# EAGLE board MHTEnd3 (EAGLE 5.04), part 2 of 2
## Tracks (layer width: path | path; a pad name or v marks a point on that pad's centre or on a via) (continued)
MASSE  (via drill 0.9 pad 1.5) (continued)
  Unten/V1 2.159: 144.53,142.24 143.26,140.97 143.26,136.91 | 143.26,136.91 143.26,135.89 144.53,134.62 148.34,134.62 | 150.88,129.54 G308.1 | 153.42,134.62 154.69,134.62 | 148.34,134.62 153.42,134.62 | 143.26,129.54 138.18,129.54 136.91,129.54 | 134.37,129.54 131.07,129.54 | 158.5,129.54 159.77,129.54 | 162.31,129.54 165.61,129.54 | 153.42,140.97 153.42,142.24 | 153.42,134.62 153.42,139.7 | 153.42,139.7 153.42,140.97 | 27.69,129.54 24.39,129.54 | 31.5,129.54 30.23,129.54 | 55.63,129.54 58.93,129.54 | 41.66,137.16 41.66,134.62 | 41.66,139.7 41.66,137.16 | 41.66,140.97 41.66,139.7 | 41.66,140.97 41.66,142.24 37.85,142.24 | 36.58,134.62 41.66,134.62 | 34.04,132.08 34.04,139.7 34.04,140.97 35.31,142.24 | 37.85,142.24 35.31,142.24 | 37.85,142.24 36.58,140.97 | 36.58,139.7 36.58,134.62 | 36.58,140.97 36.58,139.7 | 41.66,134.62 G117.2 | 36.58,132.08 36.58,134.62 | 35.31,142.24 35.31,132.08 | 153.42,140.97 152.15,142.24 | 149.61,142.24 152.15,142.24 | 148.34,142.24 149.61,142.24 | 148.34,142.24 144.53,142.24 | C105.2 37.85,185.42 | C108.1 42.93,185.42 | 96.27,201.93 J2.2 93.73,201.93 91.19,204.47 | C308.1 147.07,182.88 | C305.2 152.15,182.88 | 155.96,139.7 R315.2 | 158.25,129.79 158.25,133.6 155.96,135.89 | 152.15,142.24 149.61,144.78 | 144.53,142.24 144.53,143.51 | 41.66,139.7 36.58,139.7 | 36.58,140.97 41.66,140.97 | 45.47,143.51 45.47,142.24 46.74,140.97 46.74,138.43 45.47,137.16 | 45.47,137.16 42.93,134.62 41.66,134.62 | 40.39,144.78 37.85,142.24 | 41.66,137.16 45.47,137.16 | 44.2,143.51 41.66,140.97 | 153.42,139.7 152.15,139.7 | 152.15,139.7 149.61,142.24 | 148.34,136.91 148.34,139.7 | 148.34,139.7 148.34,142.24 | 148.34,134.62 148.34,136.91 | 148.34,136.91 143.26,136.91
  Unten/V1 2.159: 148.34,139.7 152.15,139.7
  Unten/V1 2.54: 154.69,142.24 153.42,142.24 | 154.69,142.24 155.96,140.97 155.96,139.7 155.71,139.45 155.71,136.91 | G308.1 155.71,136.91 | 154.69,134.62 154.69,142.24 | 155.71,136.91 155.71,134.87 155.96,134.62 | v95,129.54 T1.11 | v95,129.54 T2.11 | v95,129.54 95,120.14
  Unten/V1 2.794: C128.1 51.82,81.28 J103.2 J103.1 J101.2 | C119.2 41.66,81.28 J101.1 J101.2 | 46.74,78.74 J101.2 | 150.88,129.54 G309.1 148.34,127 G314.2 | 150.88,129.54 158.5,129.54 | 153.42,127 155.96,127 158.5,129.54 | 150.88,129.54 143.26,129.54 | 150.88,129.54 153.42,129.54 | G108.1 39.12,129.54 | 39.12,129.54 G109.1 41.66,127 | 36.58,127 34.04,127 31.5,129.54 | 51.82,129.54 49.28,127 46.74,127 G118.2 | G117.2 44.2,129.54 | G118.2 44.2,129.54 | G108.1 36.58,132.08 35.31,132.08 34.04,132.08 32.77,132.08 32.77,130.81 31.5,129.54 | 44.2,129.54 51.82,129.54 | 39.12,129.54 31.5,129.54 | C328.1 138.18,81.28 J303.1 J303.2 143.26,78.74 | C319.2 148.34,81.28 J301.1 143.26,78.74 | J301.2 143.26,78.74 | 143.26,127 G314.2 | 41.66,127 G118.2 | 41.66,134.62 41.66,127 | G108.1 G117.2 | 51.82,129.54 49.28,132.08 G117.2 | G313.2 148.34,132.08 | 148.34,132.08 G308.1 155.96,132.08 | G313.2 140.72,132.08 | 140.72,132.08 138.18,129.54 140.72,127 G314.2 | G314.2 G313.2 | 158.5,129.54 158.25,129.79 155.96,132.08 | 148.34,132.08 148.34,134.62 143.26,134.62 140.72,132.08 | 155.96,132.08 155.96,134.62 | 93.73,201.93 93.73,204.47 | 93.73,204.47 92.46,205.74 v93.73,205.74 51.82,205.74 40.39,194.31 40.39,156.21 | 96.27,201.93 96.27,205.74 v93.73,208.28 50.55,208.28 37.85,195.58 37.85,185.42 37.85,161.29 | 93.73,204.47 91.19,204.47 84.84,204.47 83.57,203.2 53.09,203.2 42.93,193.04 42.93,185.42 42.93,156.21 40.39,156.21 | v107.7,205.74 140.72,205.74 149.61,196.85 149.61,182.88 | v107.7,205.74 v107.7,203.2 139.45,203.2 147.07,195.58 147.07,182.88 149.61,182.88 | 149.61,182.88 152.15,182.88 152.15,198.12 141.99,208.28 v110.24,208.28 v107.7,205.74
  Unten/V1 2.794: 144.53,147.32 148.34,151.13 149.61,151.13 | 147.07,158.75 149.61,158.75 | 154.69,158.75 152.15,158.75 | 37.85,156.21 35.31,156.21 35.31,158.75 37.85,161.29 | 40.39,156.21 37.85,156.21 | 37.85,161.29 37.85,156.21 | 37.85,151.13 36.58,151.13 | 35.31,151.13 36.58,151.13 | 40.39,151.13 37.85,151.13 | 40.39,151.13 42.93,151.13 | 37.85,156.21 37.85,151.13 | 40.39,156.21 40.39,151.13 | 42.93,151.13 45.47,151.13 45.47,143.51 44.2,143.51 42.93,143.51 | 42.93,151.13 42.93,143.51 | 40.39,151.13 40.39,147.32 | 40.39,147.32 40.39,144.78 40.39,143.51 42.93,143.51 | 40.39,147.32 36.58,151.13 | 149.61,151.13 152.15,151.13 | 152.15,151.13 154.69,151.13 153.42,149.86 | 152.15,156.21 154.69,156.21 | 152.15,156.21 149.61,156.21 | 149.61,156.21 147.58,156.21 | 149.61,151.13 149.61,156.21 | 152.15,151.13 152.15,156.21
  Unten/V1 3.302: C126.1 C127.1 | C127.1 C128.1 46.74,86.36 | C118.2 C119.2 46.74,86.36 | C117.2 C118.2 | 46.74,111.76 C117.2 | 46.74,111.76 C126.1 | 46.74,99.06 C127.1 | 46.74,99.06 C118.2 | 46.74,86.36 46.74,78.74 | 46.74,99.06 46.74,86.36 | 46.74,111.76 46.74,99.06 | C317.2 143.26,111.76 | C326.1 143.26,111.76 | C327.1 143.26,99.06 | C318.2 143.26,99.06 | 143.26,86.36 C319.2 C318.2 | 143.26,86.36 C328.1 C327.1 | C317.2 C318.2 | C326.1 C327.1 | 143.26,86.36 143.26,78.74 | 143.26,99.06 143.26,86.36 | 143.26,111.76 143.26,99.06 | 143.26,111.76 v143.26,121.92 148.34,127 | G109.1 36.58,127 41.66,121.92 C117.2 | 46.74,127 51.82,121.92 C126.1 | 143.26,127 138.18,121.92 C326.1 | 46.74,111.76 v46.74,121.92 41.66,127 | G309.1 153.42,127 148.34,121.92 C317.2 | 144.53,143.51 144.53,147.32 | 149.61,158.75 149.61,158.24 | 147.07,143.51 147.07,146.05 149.61,148.59 | 149.61,146.05 149.61,148.59 | 149.61,146.05 149.61,144.78 149.61,143.51 | 149.61,148.59 152.15,151.13 | 154.69,156.21 154.69,158.75 | 149.61,146.05 153.42,149.86 | 147.07,182.88 147.07,158.75 | 152.15,182.88 152.15,158.75 149.61,158.75 | 149.61,182.88 149.61,158.75
N$1
  Oben/V2 1.016: C121.1 41.66,10.16 C125.1
  Unten/V1 1.016: C125.1 R185.2
N$2
  Oben/V2 1.016: C125.2 56.9,15.24 R182.1
  Unten/V1 1.016: IC102.3 50.55,22.86 51.82,21.59 51.82,16.51 C125.2
N$3
  Oben/V2 1.016: R159.1 IC103.1
  Unten/V1 1.016: R158.2 30.23,20.32 32.77,17.78 R159.1
N$4
  Oben/V2 1.016: IC103.3 36.58,6.35 37.85,5.08 75.95,5.08 79.76,8.89 G138.1
  Unten/V1 1.016: IC103.3 36.58,20.32 | MP11.1 R156.2 30.23,25.4 31.5,24.13 31.5,21.59 32.77,20.32 R158.1 36.58,20.32 | 36.58,20.32 V125.2
N$5
  Unten/V1 1.016: V125.1 IC102.7
N$6
  Oben/V2 1.016: IC104.1 56.9,17.78 R181.1
  Unten/V1 1.016: R181.1 R183.2
N$7
  Oben/V2 1.016: 64.52,20.32 G135.2 | R181.2 64.52,20.32 | MP12.1 81.03,22.86 78.49,20.32 64.52,20.32
  Unten/V1 1.016: IC104.2 V130.2 | V130.2 R181.2 | V130.2 R174.1
N$8
  Unten/V1 1.016: IC102.4 50.55,25.4 53.09,22.86 V130.1
N$9
  Unten/V1 1.016: C124.1 44.2,21.59 42.93,22.86 | 42.93,22.86 IC102.6 | 42.93,22.86 44.2,24.13 R170.1 C123.1 42.93,30.48 41.66,31.75 R161.2 | R168.1 42.93,35.56 41.66,34.29 R161.2 | R161.2 C120.2
N$10
  Oben/V2 1.016: R169.1 48.01,33.02 46.74,31.75 46.74,21.59 48.01,20.32 | R171.1 46.74,15.24 | 48.01,20.32 IC102.2 | 48.01,20.32 46.74,19.05 46.74,15.24 | 46.74,15.24 C124.2
N$11
  Oben/V2 1.016: R169.2 45.47,33.02 46.74,34.29 46.74,36.83 45.47,38.1 R167.2 C122.2
N$12
  Unten/V1 1.016: V305.2 176.28,149.86 176.28,140.97 177.55,139.7 | 177.55,139.7 R309.1 | 177.55,139.7 176.28,138.43 G305.2
N$13
  Unten/V1 1.016: R157.2 V125.3
N$14
  Unten/V1 1.016: V130.3 R180.1
N$15
  Oben/V2 1.016: R153.2 35.31,35.56 34.04,34.29 34.04,31.75 32.77,30.48 R155.2
  Unten/V1 1.016: R155.2 30.23,30.48 22.61,38.1 V120.3
N$16
  Oben/V2 1.016: R160.2 R173.2
  Unten/V1 1.016: R160.2 39.12,48.26 36.58,50.8 V123.2 36.58,55.88 R151.2 | R173.2 53.09,49.53 55.63,49.53 56.9,50.8 V126.2 56.9,58.42 | C129.2 56.9,59.69 56.9,58.42 | 56.9,58.42 R175.2
N$17
  Oben/V2 0.762: V124.3 26.72,35.87 26.42,35.56 28.96,33.02 R154.2
N$18
  Oben/V2 1.016: 51.82,55.88 51.82,63.5 R162.2 | R165.2 51.82,55.88 | V133.2 73.41,35.56 77.22,39.37 77.22,49.53 73.41,53.34 V132.1 69.6,55.88 60.71,55.88 59.44,54.61 | 51.82,55.88 52.58,56.64 57.41,56.64 59.44,54.61 | 59.44,54.61 V126.1
N$19
  Oben/V2 0.762: V124.2 26.42,38.1 25.15,38.1
  Oben/V2 1.016: 25.15,38.1 23.88,36.83 23.88,34.29 22.61,33.02 V120.1
  Unten/V1 1.016: R157.1 25.15,22.86 21.34,26.67 V120.1
N$20
  Oben/V2 0.762: V124.1 28.66,37.8 28.96,38.1 R152.1
N$21
  Oben/V2 0.762: V124.4 28.63,35.89 28.96,35.56 R153.1
N$22
  Oben/V2 0.762: V129.3 66.75,32.72 67.06,33.02 64.52,35.56 R177.1
N$23  (via drill 0.9 pad 1.5)
  Oben/V2 1.524: G128.1 16.26,58.42 18.8,60.96 18.8,62.23 20.07,63.5 v26.42,63.5
  Unten/V1 1.016: V118.1 29.29,93.98 C116.1
  Unten/V1 1.524: 25.15,50.8 23.88,49.53 23.88,44.45 22.61,43.18 G129.1 R149.1 | 25.15,50.8 23.88,52.07 23.88,54.61 22.61,55.88 16.26,55.88 G128.1 9.91,62.23 G127.2 | 25.15,50.8 V121.2 | v26.42,63.5 26.42,76.2 28.96,78.74 V118.1
N$24
  Unten/V1 1.524: 23.88,58.42 R145.2 | V121.1 26.42,55.88 23.88,58.42 | G127.1 20.07,58.42 23.88,58.42
N$25
  Unten/V1 1.016: J107.1 86.11,5.08 83.57,7.62 67.06,7.62 MP7.1 R185.1
N$26
  Oben/V2 1.524: R136.1 R135.1 26.42,116.84 26.42,114.3 | R137.1 R136.1 | R138.1 R137.1 | R138.1 R139.1 26.42,106.68 26.42,109.22 | R141.1 R140.1 26.42,91.44 26.42,88.9 | R142.1 R141.1 | R143.1 R142.1 | R143.1 R144.1 26.42,81.28 26.42,83.82 | 26.42,111.76 26.42,114.3 | 26.42,109.22 26.42,111.76 | 26.42,86.36 26.42,88.9 | 26.42,83.82 26.42,86.36 | R143.1 26.42,83.82 | R142.1 26.42,86.36 | R141.1 26.42,88.9 | R138.1 26.42,109.22 | R137.1 26.42,111.76 | R136.1 26.42,114.3
  Oben/V2 1.778: V118.3 28.96,104.14 26.42,104.14 | 26.42,104.14 23.88,104.14 R139.1 | 26.42,106.68 26.42,104.14
  Oben/V2 2.159: 28.96,104.14 28.96,106.68 26.42,106.68
  Unten/V1 1.524: R136.1 R135.1 | R137.1 R136.1 | R138.1 R137.1 | R144.1 R143.1 | R143.1 R142.1 | R142.1 R141.1 | R141.1 R140.1 | R140.1 23.88,104.14 R139.1 | R139.1 R138.1 | R144.1 20.07,81.28 | R135.1 21.34,116.84 20.07,115.57 | R136.1 20.07,114.3 | R137.1 20.07,111.76 | R138.1 20.07,109.22 | R139.1 20.07,106.68 | R140.1 20.07,91.44 | R141.1 20.07,88.9 | R142.1 20.07,86.36 | R143.1 20.07,83.82 | R144.1 22.61,81.28 21.34,80.01 21.34,71.12 | R135.1 26.42,116.84 26.42,114.3 | 26.42,111.76 26.42,114.3 | 26.42,109.22 26.42,111.76 | 26.42,106.68 26.42,109.22 | 26.42,91.44 26.42,91.95 25.91,92.46 25.91,94.74 26.42,95.25 26.42,97.54 25.91,98.04 25.91,100.08 26.42,100.58 26.42,101.6 26.42,104.14 26.42,106.68 | 26.42,88.9 26.42,91.44 | 26.42,86.36 26.42,88.9 | 26.42,83.82 26.42,86.36 | 26.42,83.82 26.42,81.28 R144.1 | R143.1 26.42,83.82 | R142.1 26.42,86.36 | R141.1 26.42,88.9 | R140.1 26.42,91.44 | R139.1 26.42,106.68 | R138.1 26.42,109.22 | R137.1 26.42,111.76 | R136.1 26.42,114.3 | R146.1 21.34,71.12 | 21.34,71.12 R147.2
  Unten/V1 1.778: 26.42,106.68 28.96,106.68 V118.3 28.96,104.14 26.42,104.14 23.88,104.14 20.07,104.14
  Unten/V1 2.159: 28.96,104.14 28.96,102.87 27.69,102.87 26.42,101.6 20.07,101.6
  Unten/V1 2.794: 20.07,81.28 20.07,83.82 20.07,86.36 20.07,88.9 20.07,91.44 20.07,101.6 20.07,104.14 20.07,106.68 20.07,109.22 20.07,111.76 20.07,114.3 20.07,115.57
N$27
  Oben/V2 0.762: V129.2 67.06,30.48 67.06,29.97 66.3,29.21 65.79,29.21 64.52,27.94
  Oben/V2 1.016: R180.2 64.52,27.94
  Unten/V1 1.016: R180.2 63.25,27.94 67.06,31.75 67.06,36.83 68.33,38.1 V133.1
N$28
  Oben/V2 0.762: V129.1 64.83,30.79 64.52,30.48 R179.2
N$29  (via drill 0.9 pad 1.5, 3.2 pad 5.99)
  Oben/V2 1.524: v11.18,121.92 11.18,112.53 v12.45,111.26
N$30
  Oben/V2 0.762: V129.4 64.83,32.72 64.52,33.02 R178.1
N$31
  Oben/V2 1.016: R178.2 58.17,33.02 59.44,34.29 59.44,36.83 60.71,38.1 R176.1 64.52,38.1 69.6,33.02 V133.3
N$32
  Unten/V1 1.016: V122.3 28.96,57.15 26.42,59.69 R147.1
N$33
  Unten/V1 1.016: R150.1 G129.2 27.69,43.18 26.42,44.45 V121.3 V122.1
N$34  (via drill 3.2 pad 5.99)
  other vias: 12.45,86.86
N$35
  Oben/V2 1.524: R187.1 R186.1 67.06,116.84 67.06,114.3 | R188.1 R187.1 | R189.1 R188.1 | R189.1 R190.1 67.06,106.68 67.06,109.22 | R192.1 R191.1 67.06,91.44 | R193.1 R192.1 | R194.1 R193.1 | R194.1 R195.1 67.06,81.28 67.06,83.82 | R187.1 67.06,114.3 | R188.1 67.06,111.76 | R189.1 67.06,109.22 | 67.06,109.22 67.06,111.76 | 67.06,111.76 67.06,114.3 | 67.06,88.9 67.06,91.44 | 67.06,86.36 67.06,88.9 | 67.06,83.82 67.06,86.36 | R194.1 67.06,83.82 | R193.1 67.06,86.36 | R192.1 67.06,88.9 | 64.52,93.98 65.79,93.98 67.06,92.71 67.06,91.44
  Oben/V2 2.159: 67.06,91.44 64.52,91.44 64.52,93.98
  Unten/V1 1.524: R195.1 R194.1 | R194.1 R193.1 | R193.1 R192.1 | R192.1 R191.1 | R191.1 R190.1 | R190.1 R189.1 | R189.1 R188.1 | R188.1 R187.1 | R187.1 R186.1 | R186.1 72.14,116.84 73.41,115.57 | R187.1 73.41,114.3 | R188.1 73.41,111.76 | R191.1 73.41,91.44 | R192.1 73.41,88.9 | R193.1 73.41,86.36 | R194.1 73.41,83.82 | R195.1 73.41,81.28 | R189.1 73.41,109.22 | R190.1 73.41,106.68 | R186.1 67.06,116.84 67.06,114.3 | 67.06,111.76 67.06,114.3 | 67.06,109.22 67.06,111.76 | 67.06,106.68 67.06,109.22 | 67.06,91.44 67.06,95.25 67.06,97.54 67.57,98.04 67.57,100.08 67.06,100.58 67.06,103.12 67.57,103.63 67.57,105.41 67.06,105.92 67.06,106.68 | 67.06,88.9 67.06,91.44 | 67.06,86.36 67.06,88.9 | 67.06,83.82 67.06,86.36 | 67.06,83.82 67.06,81.28 R195.1 | R194.1 67.06,83.82 | R193.1 67.06,86.36 | R192.1 67.06,88.9 | R191.1 67.06,91.44 | R190.1 67.06,106.68 | R189.1 67.06,109.22 | R188.1 67.06,111.76 | R187.1 67.06,114.3 | R197.2 72.14,64.77 72.14,71.12 | 72.14,71.12 R205.2 | 72.14,71.12 72.14,80.01 70.87,81.28 R195.1
  Unten/V1 2.159: 64.52,91.44 V131.3 64.52,95.25 67.06,95.25 73.41,95.25 | 67.06,91.44 64.52,91.44 | 64.52,91.44 64.52,90.17 65.79,88.9 67.06,88.9
  Unten/V1 2.794: 73.41,115.57 73.41,114.3 73.41,111.76 73.41,109.22 73.41,106.68 73.41,95.25 73.41,91.44 73.41,88.9 73.41,86.36 73.41,83.82 73.41,81.28
N$36
  Unten/V1 1.524: V128.1 67.06,59.69 | 67.06,59.69 67.06,63.5 69.6,66.04 R196.1 | G132.2 74.68,59.69 67.06,59.69
N$37  (via drill 0.9 pad 1.5)
  Oben/V2 1.016: G134.2 70.87,43.18 69.6,44.45 69.6,49.53 68.33,50.8 V128.2
  Oben/V2 1.524: V131.1 64.52,104.14 v77.22,104.14
  Unten/V1 1.016: V131.1 64.52,104.14 C130.2
  Unten/V1 1.524: 87.38,58.42 74.68,45.72 R206.2 G134.2 | 87.38,58.42 G133.2 | 87.38,58.42 G132.1 87.38,71.12 77.22,81.28 77.22,83.57 76.46,84.33 76.46,89.15 77.22,89.92 v77.22,104.14
N$38
  Unten/V1 1.524: G131.1 G133.1 79.76,57.15 73.41,50.8 V132.2
N$39
  Unten/V1 1.524: G131.2 R205.1
N$40
  Unten/V1 1.016: V127.3 R197.1
N$41
  Unten/V1 1.524: V127.1 V128.3 67.06,44.45 65.79,43.18 G134.1 R199.2
N$42
  Oben/V2 1.016: V119.3 20.07,53.34 18.8,52.07 18.8,46.99 20.07,45.72 R148.1
N$43
  Oben/V2 1.016: R201.2 68.33,10.16 61.98,16.51 R184.2
  Unten/V1 1.016: R184.2 64.52,20.32 73.41,20.32 77.22,24.13 IC105.1 C131.2 | R201.2 R202.2
N$44
  Unten/V1 1.016: R200.1 C131.1 73.41,27.94 74.68,26.67 IC105.2
N$45
  Unten/V1 1.016: G136.2 IC105.5 R201.1
N$46
  Oben/V2 1.016: R202.1 72.14,13.97 74.68,11.43 R203.2
  Unten/V1 1.016: R202.1 IC105.6 | R203.2 R204.1
N$47
  Oben/V2 1.016: G137.1 82.3,26.67 78.49,22.86 70.87,22.86 69.6,24.13 IC105.4
  Unten/V1 1.016: G135.1 64.52,26.67 65.79,27.94 68.33,27.94 69.6,26.67 IC105.4
N$48  (via drill 3.2 pad 5.99)
  other vias: 18.8,219.71
N$49  (via drill 3.2 pad 5.99)
  other vias: 54.36,219.71
N$50  (via drill 3.2 pad 5.99)
  other vias: 81.03,111.26
N$51  (via drill 3.2 pad 5.99)
  other vias: 81.03,86.86
N$52  (via drill 0.9 pad 1.5)
  Oben/V2 1.016: C122.1 R167.1 | R148.2 31.5,45.72 33.28,47.5 39.12,47.5 40.9,45.72 46.74,45.72 C122.1 | R200.2 69.6,41.91 65.79,45.72 R198.1 60.71,45.72 58.17,48.26 55.63,48.26 53.09,45.72 51.82,45.72 C122.1
  Oben/V2 1.524: 18.8,69.85 G126.1 | 74.68,69.85 G130.2 | J102.1 46.74,68.58 46.74,52.07 48.01,50.8 v49.28,50.8
  Oben/V2 2.159: 26.42,99.06 V118.2 | V118.2 28.96,100.33 26.42,100.33 | 28.96,98.04 V118.2 | 26.42,96.52 27.44,96.52 28.96,98.04 | 26.42,97.79 27.69,97.79 28.71,97.79 28.96,98.04 | 64.52,97.79 V131.2 | 68.33,96.52 67.06,96.52 65.79,97.79 64.52,97.79 | 67.06,99.06 V131.2 | 67.06,101.09 66.81,101.35 65.54,101.35 64.52,100.33 | V131.2 64.52,100.33 | 67.06,100.33 64.52,100.33 | 67.06,97.79 64.52,97.79
  Oben/V2 2.54: 81.03,97.79 81.03,104.14 74.68,110.49 74.68,123.19 82.3,130.81 T1.12
  Oben/V2 2.794: 44.2,69.85 39.12,69.85 | 20.07,72.39 20.07,69.85 18.8,69.85 | 20.07,72.39 20.07,74.93 | 20.07,74.93 20.07,76.2 | 18.8,69.85 18.29,69.85 17.53,70.61 | 73.41,69.85 73.41,73.66 | 73.41,73.66 73.41,76.2 | 73.41,76.2 73.41,94.49 70.36,94.49 68.33,96.52 | 74.68,69.85 74.93,69.85 75.95,70.87 | 44.2,69.85 J102.1 44.2,72.39 | 44.2,69.85 74.68,69.85 | 73.41,69.85 72.14,71.12 J104.1 J104.2 50.55,72.39 | 44.2,72.39 50.55,72.39 | 56.9,74.93 56.9,73.66 55.63,72.39 50.55,72.39 | 50.55,72.39 70.87,72.39 | 39.12,69.85 18.8,69.85 | 39.12,69.85 J102.2 37.85,72.39 | 26.42,72.39 20.07,72.39 | 37.85,72.39 26.42,72.39 | 37.85,72.39 36.58,73.66 | 36.58,73.66 36.58,74.93 | 36.58,74.93 35.31,76.2 34.04,76.2 32.77,74.93 30.23,74.93 | 20.07,76.2 21.34,76.2 22.61,74.93 | 22.61,74.93 25.15,74.93 | 25.15,74.93 26.42,76.2 28.96,76.2 30.23,74.93 | 17.53,70.61 14.99,73.15 | 56.9,74.93 58.17,76.2 59.44,76.2 60.71,74.93 63.25,74.93 64.52,76.2 67.06,76.2 68.33,74.93 70.87,74.93 72.14,76.2 73.41,76.2 | 75.95,70.87 75.95,95.25 74.68,96.52 68.33,96.52 | 75.95,70.87 78.49,73.41 | 78.49,73.41 78.49,76.96 86.11,84.58 86.11,88.9 75.95,99.06 67.06,99.06 | 78.49,73.41 88.65,83.57 88.65,90.17 81.03,97.79 77.73,101.09 67.06,101.09 67.06,100.33 67.06,99.06 | 44.2,72.39 37.85,72.39 | 36.58,73.66 34.04,73.66 32.77,72.39 26.42,72.39 | 74.68,69.85 73.41,69.85 | 25.15,74.93 30.23,74.93 | 20.07,74.93 22.61,74.93 | 56.9,74.93 58.17,73.66 73.41,73.66 | 36.58,74.93 56.9,74.93 | 20.07,76.2 20.07,93.98 20.58,94.49 25.15,94.49 25.15,95.25 26.42,96.52 | 26.42,99.06 26.42,97.79 26.42,96.52 | 26.42,99.06 26.42,100.33 14.99,100.33 4.83,90.17 4.83,83.31 14.99,73.15
  Oben/V2 2.794: 17.53,70.61 17.53,95.25 18.8,96.52 26.42,96.52 | 14.99,73.15 14.99,76.96 7.37,84.58 7.37,88.9 17.53,99.06 26.42,99.06 | 68.33,96.52 68.33,97.79 67.06,97.79 67.06,99.06
  Unten/V1 1.016: R170.2 C123.2 50.55,30.48 51.82,31.75 51.82,33.02 R168.2 R167.1 | V118.2 C116.2 | V131.2 C130.1
  Unten/V1 1.524: C122.1 v49.28,50.8
N$54
  Oben/V2 1.016: R382.1 130.56,16.51 131.83,15.24 C325.2
  Unten/V1 1.016: IC302.3 139.45,20.32 138.18,19.05 138.18,16.51 C325.2
N$55
  Unten/V1 1.016: R358.2 159.77,20.32 157.23,17.78 R359.1 IC303.1
N$56
  Oben/V2 1.016: IC303.3 153.42,12.7 153.42,6.35 152.15,5.08 114.05,5.08 110.24,8.89 G338.1
  Unten/V1 1.016: 155.96,22.86 R358.1 | 155.96,22.86 R357.2 MP9.1 | IC303.3 V325.2 153.42,22.86 155.96,22.86
N$57
  Oben/V2 1.016: V117.2 89.92,167.64 89.92,168.91 88.65,170.18 R132.2 V116.1
N$58
  Unten/V1 1.016: R381.1 R384.2 IC304.1
N$59
  Oben/V2 1.016: IC302.4 139.45,17.78 138.18,19.05 138.18,21.59 136.91,22.86 V330.1
N$60
  Oben/V2 1.016: R361.2 148.34,34.29 150.88,36.83 C320.2
  Unten/V1 1.016: C324.1 145.8,19.05 147.07,20.32 | 147.07,20.32 IC302.6 | 147.07,20.32 145.8,21.59 R370.1 C323.1 147.07,30.48 148.34,31.75 R361.2 148.34,34.04 146.82,35.56 R368.1
N$61
  Oben/V2 1.016: 141.99,22.86 IC302.2 | R369.1 141.99,33.02 143.26,31.75 143.26,24.13 141.99,22.86 | 143.26,15.24 143.26,21.59 141.99,22.86 | 143.26,15.24 R371.1 | C324.2 143.26,15.24
N$62
  Oben/V2 1.016: R369.2 144.53,33.02 143.26,34.29 143.26,36.83 144.53,38.1 R367.2 C322.2
N$63
  Oben/V2 1.016: V325.3 R356.2
N$64
  Unten/V1 1.016: V330.3 R380.1
N$65
  Oben/V2 1.016: R354.2 154.69,33.02 155.96,34.29 155.96,36.83 157.23,38.1 R352.2
  Unten/V1 1.016: R352.2 161.04,38.1 166.12,33.02 V320.3
N$66
  Oben/V2 1.016: V320.2 169.93,35.56 173.74,39.37 173.74,49.53 169.93,53.34 V319.1 166.12,55.88 157.23,55.88 155.96,54.61 | 155.96,52.07 V323.1 155.96,54.61 | R365.1 148.85,55.88 149.61,56.64 153.93,56.64 155.96,54.61
  Unten/V1 1.016: R363.1 148.34,59.69 148.34,57.15 147.07,55.88 R365.1
N$67
  Oben/V2 0.762: R353.2 161.04,35.56 163.58,33.02 163.28,32.72 V324.3
N$68
  Oben/V2 0.762: V324.2 163.58,30.48 164.85,30.48
  Oben/V2 1.016: 164.85,30.48 166.12,31.75 166.12,36.83 167.39,38.1 V320.1
  Unten/V1 1.016: V320.1 169.93,38.1 171.2,36.83 171.2,31.75 167.39,27.94 R356.1
N$69
  Oben/V2 0.762: V324.1 161.34,30.79 161.04,30.48 R355.1
N$70
  Oben/V2 0.762: V324.4 161.34,32.72 161.04,33.02 R354.1
N$71  (via drill 3.2 pad 5.99)
  other vias: 108.97,111.26
N$72
  Unten/V1 1.016: IC302.7 V325.1
N$73
  Unten/V1 1.524: R345.2 166.12,66.04 163.58,63.5 163.58,59.69 | V321.1 163.58,59.69 | G327.1 171.2,59.69 163.58,59.69
N$74
  Oben/V2 1.524: R336.1 R335.1 163.58,116.84 163.58,114.3 | R337.1 R336.1 | R338.1 R337.1 | R343.1 R344.1 163.58,81.28 163.58,83.82 | R342.1 R343.1 | R341.1 R342.1 | R341.1 R340.1 163.58,91.44 163.58,88.9 | R338.1 R339.1 163.58,106.68 163.58,109.22 | 163.58,111.76 163.58,114.3 | 163.58,109.22 163.58,111.76 | 163.58,88.9 163.58,86.36 | 163.58,86.36 163.58,83.82 | R343.1 163.58,83.82 | R342.1 163.58,86.36 | R341.1 163.58,88.9 | R338.1 163.58,109.22 | R337.1 163.58,111.76 | R336.1 163.58,114.3
  Oben/V2 2.159: V318.3 161.04,92.71 162.31,91.44 163.58,91.44
  Unten/V1 1.524: R344.1 168.66,81.28 | 169.93,81.28 168.66,81.28 | R335.1 168.66,116.84 169.93,115.57 | 169.93,114.3 R336.1 | R337.1 169.93,111.76 | 169.93,109.22 R338.1 | R339.1 169.93,106.68 | R340.1 169.93,91.44 | R341.1 169.93,88.9 | R342.1 169.93,86.36 | R343.1 169.93,83.82 | R336.1 R335.1 | R337.1 R336.1 | R338.1 R337.1 | R339.1 R338.1 | R340.1 166.12,95.25 | 166.12,95.25 R339.1 | R341.1 R340.1 | R341.1 R342.1 | R342.1 R343.1 | R343.1 R344.1 | 168.66,71.12 R346.1 | 168.66,81.28 168.66,71.12 | 168.66,71.12 168.66,64.77 R347.2 | R335.1 163.58,116.84 163.58,114.3 | 163.58,111.76 163.58,114.3 | 163.58,109.22 163.58,111.76 | 163.58,106.68 163.58,109.22 | 163.58,91.44 163.58,95.25 | 163.58,95.25 163.58,97.54 164.09,98.04 164.09,100.08 163.58,100.58 163.58,103.12 164.09,103.63 164.09,105.41 163.58,105.92 163.58,106.68 | 163.58,88.9 163.58,91.44 | 163.58,88.9 163.58,86.36 | 163.58,86.36 163.58,83.82 | 163.58,83.82 163.58,81.28 R344.1 | R343.1 163.58,83.82 | R342.1 163.58,86.36 | R341.1 163.58,88.9 | R340.1 163.58,91.44 | R339.1 163.58,106.68 | R338.1 163.58,109.22 | R337.1 163.58,111.76 | R336.1 163.58,114.3 | 163.58,95.25 162.31,95.25 161.04,93.98 161.04,92.71 162.31,91.44 163.58,91.44 | 166.12,95.25 163.58,95.25
  Unten/V1 2.794: 169.93,81.28 169.93,83.82 169.93,86.36 169.93,88.9 169.93,91.44 169.93,106.68 169.93,109.22 169.93,111.76 169.93,114.3 169.93,115.57
N$75
  Oben/V2 0.762: V329.2 122.94,30.48 125.48,27.94 R380.2
  Unten/V1 1.016: R380.2 126.75,27.94 121.67,33.02 V333.1
N$76
  Oben/V2 0.762: V329.1 123.24,32.72 122.94,33.02
  Oben/V2 1.016: R377.2 125.48,35.56 122.94,33.02
N$77
  Oben/V2 0.762: V329.3 125.17,30.79 125.48,30.48
  Oben/V2 1.016: 125.48,30.48 R379.1
N$78
  Oben/V2 0.762: V329.4 125.17,32.72 125.48,33.02
  Oben/V2 1.016: 125.48,33.02 R378.1
N$79
  Oben/V2 1.016: R376.1 129.29,38.1 130.56,36.83 130.56,34.29 131.83,33.02 R378.2
  Unten/V1 1.016: V333.3 R376.1
N$80
  Oben/V2 1.016: R362.2 138.18,63.5 138.18,55.88 | 138.18,55.88 R366.2 | V332.1 119.13,48.26 120.4,49.53 120.4,54.61 121.67,55.88 128.02,55.88 128.53,56.39 135.13,56.39 135.64,55.88 | 135.64,55.88 V326.1 | 135.64,55.88 138.18,55.88
  Unten/V1 1.016: V333.2 116.59,35.56 112.78,39.37 112.78,44.45 116.59,48.26 V332.1
N$81
  Unten/V1 1.016: R130.1 R131.2 V116.3
N$82
  Oben/V2 1.524: R394.1 R395.1 122.94,81.28 122.94,83.82 | R394.1 R393.1 | R393.1 R392.1 | R392.1 R391.1 122.94,91.44 122.94,88.9 | R389.1 R390.1 122.94,106.68 | R389.1 R388.1 | R388.1 R387.1 | R387.1 R386.1 122.94,116.84 122.94,114.3 | 122.94,111.76 122.94,114.3 | 122.94,109.22 122.94,111.76 | 122.94,106.68 122.94,109.22 | 122.94,86.36 122.94,88.9 | 122.94,83.82 122.94,86.36 | R387.1 122.94,114.3 | R388.1 122.94,111.76 | R389.1 122.94,109.22 | R392.1 122.94,88.9 | R393.1 122.94,86.36 | R394.1 122.94,83.82 | 122.94,106.68 122.94,105.41 124.21,104.14 125.48,104.14 125.48,105.41 | 125.48,105.41 124.21,106.68 122.94,106.68 | 125.48,105.41 125.48,107.95 124.21,109.22 122.94,109.22
  Unten/V1 1.524: R386.1 117.86,116.84 116.59,115.57 | 116.59,114.3 R387.1 | R388.1 116.59,111.76 | 116.59,91.44 R391.1 | R392.1 116.59,88.9 | 116.59,86.36 R393.1 | R394.1 116.59,83.82 | 117.86,81.28 116.59,81.28 | 117.86,81.28 R395.1 | 116.59,109.22 R389.1 | R390.1 116.59,106.68 | R387.1 R386.1 | R388.1 R387.1 | R389.1 R388.1 | R390.1 R389.1 | R391.1 R390.1 | R392.1 R391.1 | R393.1 R392.1 | R394.1 R393.1 | R395.1 R394.1 | R386.1 122.94,116.84 122.94,114.3 | 122.94,111.76 122.94,114.3 | 122.94,109.22 122.94,111.76 | 122.94,106.68 122.94,109.22 | 122.94,91.44 122.94,91.95 122.43,92.46 122.43,94.74 122.94,95.25 122.94,97.03 122.43,97.54 122.43,100.08 122.94,100.58 122.94,102.87 122.94,106.68 | 122.94,88.9 122.94,91.44 | 122.94,86.36 122.94,88.9 | 122.94,83.82 122.94,86.36 | 122.94,83.82 122.94,81.28 R395.1 | R394.1 122.94,83.82 | R393.1 122.94,86.36 | R392.1 122.94,88.9 | R391.1 122.94,91.44 | R390.1 122.94,106.68 | R389.1 122.94,109.22 | R388.1 122.94,111.76 | R387.1 122.94,114.3 | 117.86,71.12 R405.2 | R397.2 117.86,71.12 | 117.86,71.12 117.86,81.28
  Unten/V1 2.159: 125.48,104.14 125.48,102.87 122.94,102.87 | 125.48,104.14 V331.3 | 125.48,106.68 125.48,104.14 | 122.94,106.68 125.48,106.68 | 125.48,106.68 125.48,107.95 124.21,109.22 122.94,109.22
  Unten/V1 2.794: 116.59,81.28 116.59,83.82 116.59,86.36 116.59,88.9 116.59,91.44 116.59,106.68 116.59,109.22 116.59,111.76 116.59,114.3 116.59,115.57
N$83
  Unten/V1 1.524: V328.1 122.94,55.88 120.4,58.42 | 120.4,58.42 R396.1 | G332.2 116.59,58.42 120.4,58.42
N$84  (via drill 0.9 pad 1.5)
  Oben/V2 1.524: v122.94,63.5 116.59,63.5 115.32,62.23 115.32,60.96 112.78,58.42 G333.2
  Unten/V1 1.016: 125.48,93.98 C330.2
  Unten/V1 1.524: 121.67,50.8 120.4,49.53 120.4,44.45 119.13,43.18 | 119.13,43.18 G334.2 | R406.2 119.13,43.18 | 121.67,50.8 120.4,52.07 120.4,54.61 119.13,55.88 112.78,55.88 G333.2 106.43,62.23 G332.1 | 121.67,50.8 V328.2 | 125.48,93.98 V331.1 125.48,73.66 122.94,71.12 v122.94,63.5
N$85
  Unten/V1 1.016: J307.1 103.89,5.08 106.43,7.62 124.21,7.62 125.48,8.89 MP8.1 R385.1
N$86
  Unten/V1 1.016: V322.3 R347.1
N$87
  Unten/V1 1.016: R362.1 152.15,66.04 153.42,64.77 153.42,62.23 152.15,60.96 P301.1 V323.3 R360.1 R366.1
N$88
  Oben/V2 1.016: V326.3 130.56,50.8 131.83,49.53 136.91,49.53 138.18,50.8 R373.1
  Unten/V1 1.016: R363.2 R364.2 R365.2 139.45,55.88 138.18,54.61 R373.1
N$89  (via drill 0.9 pad 1.5)
  Oben/V2 1.016: 133.1,22.86 V330.2 | R381.2 128.02,24.13 129.29,22.86 133.1,22.86 | 133.1,22.86 IC304.2 | 110.24,21.59 111.51,22.86 v122.94,22.86 | 110.24,21.59 G336.2 | 110.24,21.59 108.97,22.86 MP10.1
  Unten/V1 1.016: v122.94,22.86 124.21,22.86 126.75,25.4 R381.2 | V330.2 R374.1
N$90
  Oben/V2 1.016: R373.2 R360.2
  Unten/V1 1.016: R373.2 136.91,49.53 134.37,49.53 133.1,50.8 V326.2 133.1,58.42 | R360.2 149.61,49.53 152.15,49.53 153.42,50.8 V323.2 153.42,55.88 R351.2 | 133.1,58.42 R375.2 | 133.1,58.42 C329.2
N$91
  Unten/V1 1.016: V322.1 V321.3 163.58,44.45 162.31,43.18 G329.2 R350.1
N$92
  Unten/V1 1.524: R346.2 G325.1
N$93
  Unten/V1 1.016: R184.1 R182.2 59.44,8.89 58.17,7.62 R172.2
N$94
  Oben/V2 1.016: 125.48,17.78 125.48,24.13 124.21,25.4 IC305.1 | R403.2 117.86,11.43 119.13,12.7 124.21,12.7 125.48,13.97 125.48,17.78 | 125.48,17.78 R383.2
  Unten/V1 1.016: IC305.1 C331.2 | R404.2 R403.2
N$95
  Unten/V1 1.016: IC305.2 120.4,26.67 119.13,27.94 C331.1 117.86,29.21 119.13,30.48 R400.1
N$96
  Unten/V1 1.016: G335.2 IC305.5 R404.1
N$97
  Unten/V1 1.016: IC305.6 R403.1 117.86,13.97 120.4,11.43 R402.2 R401.1
N$98
  Unten/V1 1.016: G137.2 87.38,15.24 J4.2 105.16,19.05 106.43,20.32 G337.2
N$99  (via drill 3.2 pad 5.99)
  other vias: 108.97,86.86
N$100  (via drill 0.9 pad 1.5)
  Oben/V2 2.54: 23.88,193.04 V101.3 | 32.77,190.5 30.23,190.5 | 32.77,190.5 32.77,205.74 T101.3 | 32.77,190.5 32.77,187.96 31.5,186.69
  Oben/V2 3.302: T101.3 T101.4 30.23,200.66 30.23,190.5 30.23,191.77 31.5,190.5 31.5,186.69 C105.1 30.23,185.42 26.42,189.23 26.42,190.5 23.88,193.04
  Unten/V1 1.524: v34.04,177.8 34.04,182.88 C105.1 30.23,184.15 R110.1 G107.1 | 31.5,205.74 G101.2
  Unten/V1 2.54: 31.5,186.69 32.77,187.96
  Unten/V1 3.302: 32.77,199.39 T101.4 T101.3 31.5,205.74 31.5,199.39 32.77,199.39 | 32.77,199.39 30.23,199.39 30.23,190.5 31.5,189.23 31.5,186.69 C105.1 30.23,185.42 23.88,191.77 23.88,193.04 | 32.77,187.96 32.77,199.39
N$101  (via drill 0.9 pad 1.5, 3.2 pad 5.99)
  Oben/V2 1.524: v178.82,121.92 178.82,112.53 v177.55,111.26
N$102  (via drill 3.2 pad 5.99)
  other vias: 177.55,86.86
N$103  (via drill 0.9 pad 1.5)
  Oben/V2 1.016: C322.1 R367.1 | R400.2 120.4,41.91 124.21,45.72 R398.1 128.02,45.72 129.8,47.5 135.64,47.5 137.42,45.72 138.18,45.72 C322.1 | R348.2 158.5,45.72 155.96,48.26 151.64,48.26 149.1,45.72 143.26,45.72 C322.1
  Oben/V2 1.524: 115.32,69.85 G330.2 | 143.26,71.12 143.26,52.07 141.99,50.8 v140.72,50.8 | 171.2,69.85 G326.1
  Oben/V2 2.159: V318.2 161.04,98.04 | 164.85,97.79 162.31,97.79 161.29,97.79 161.04,98.04 | V318.2 164.85,99.06 | V318.2 161.04,100.33 | 161.04,100.33 164.85,100.33 | 161.04,98.04 162.56,96.52 163.58,96.52 | 161.04,100.33 162.06,101.35 164.85,101.35 | 122.94,99.06 V331.2 | V331.2 125.48,98.04 124.21,96.77 122.94,96.77 | V331.2 125.48,100.08 123.96,101.6 122.94,101.6
  Oben/V2 2.54: T2.12 100.08,132.08 108.97,123.19 108.97,119.38 116.59,111.76 116.59,101.6
  Oben/V2 2.794: 171.2,69.85 169.93,69.85 169.93,73.66 | 169.93,76.2 169.93,73.66 | 169.93,76.2 169.93,93.98 168.66,95.25 164.85,95.25 | 172.47,69.85 175.01,72.39 | 172.47,69.85 171.2,69.85 | 116.59,73.66 116.59,76.2 | 116.59,73.66 116.59,69.85 | 116.59,76.2 116.59,93.98 117.86,95.25 121.42,95.25 122.94,96.77 122.94,99.06 | 116.59,69.85 115.32,69.85 | 115.32,69.85 114.05,69.85 | J302.1 145.8,69.85 140.72,69.85 | 135.64,69.85 115.32,69.85 | 140.72,69.85 135.64,69.85 | 116.59,69.85 119.13,69.85 120.4,71.12 J304.1 | 133.1,72.39 145.8,72.39 J302.1 | 133.1,72.39 133.1,73.66 | 116.59,73.66 117.86,72.39 121.67,72.39 122.94,73.66 133.1,73.66 | 171.2,69.85 150.88,69.85 | 150.88,69.85 J302.2 150.88,72.39 | 150.88,69.85 147.07,69.85 | 169.93,73.66 168.66,72.39 150.88,72.39 | 152.15,73.66 150.88,72.39 | 152.15,73.66 153.42,74.93 | 153.42,74.93 154.69,76.2 155.96,76.2 157.23,74.93 159.77,74.93 161.04,76.2 163.58,76.2 164.85,74.93 167.39,74.93 168.66,76.2 169.93,76.2 | 172.47,69.85 172.47,95.25 169.93,97.79 164.85,97.79 | 175.01,72.39 175.01,76.2 182.63,83.82 182.63,88.9 171.2,100.33 164.85,100.33 | 175.01,72.39 185.17,82.55 185.17,90.17 174.25,101.09 164.85,101.09 164.85,100.33 | 133.1,74.93 131.83,76.2 130.56,76.2 129.29,74.93 126.75,74.93 125.48,76.2 122.94,76.2 121.67,74.93 119.13,74.93 117.86,76.2 116.59,76.2 | 133.1,74.93 133.1,73.66 | 114.05,69.85 114.05,95.25 116.59,97.79 121.67,97.79 122.94,99.06 | 114.05,69.85 111.51,72.39 | 111.51,72.39 111.51,76.2 103.89,83.82 103.89,88.9 114.05,99.06 120.4,99.06 122.94,101.6 | 111.51,72.39 101.35,82.55 101.35,90.17 112.78,101.6 116.59,101.6 122.94,101.6 | 150.88,72.39 133.1,72.39
  Oben/V2 2.794: 169.93,73.66 152.15,73.66 | J302.1 143.26,71.12 J304.2 | J304.2 J304.1 | 135.64,69.85 J304.1 | J304.2 140.72,69.85 | 153.42,74.93 133.1,74.93 | 164.85,97.79 164.85,95.25 | 164.85,100.33 164.85,99.06 164.85,97.79 | 163.58,96.52 164.85,95.25 | 122.94,99.06 122.94,101.6
  Unten/V1 1.016: R370.2 C323.2 139.45,30.48 138.18,31.75 138.18,34.04 139.7,35.56 R368.2 R367.1 | V331.2 C330.1 | C316.2 V318.2
  Unten/V1 1.524: v140.72,50.8 C322.1
N$104
  Oben/V2 1.016: 91.19,157.48 91.19,156.46 92.46,155.19 92.46,73.66 93.73,72.39 93.73,29.21 R207.2 | 91.19,157.48 J105.1 | 91.19,157.48 C115.1
  Unten/V1 1.016: C115.1 91.19,157.48 91.19,158.75 G123.1
N$105
  Oben/V2 1.524: G306.1 161.04,165.1 R310.2
N$106
  Oben/V2 1.016: R308.2 173.74,137.16 G305.1
N$107  (via drill 0.9 pad 1.5)
  Oben/V2 1.524: V321.2 164.85,50.8 166.12,49.53 166.12,44.45 167.39,43.18 G329.1 | V318.1 161.04,104.14 v173.74,104.14
  Unten/V1 1.016: V318.1 160.71,104.14 C316.1
  Unten/V1 1.524: 183.9,58.42 171.2,45.72 R349.1 G329.1 | 183.9,58.42 G327.2 183.9,71.12 173.74,81.28 173.74,83.57 172.98,84.33 172.98,89.15 173.74,89.92 v173.74,104.14 | 183.9,58.42 G328.1
N$108
  Oben/V2 1.016: C325.1 148.34,10.16 C321.1
  Unten/V1 1.016: R385.2 C325.1
N$109
  Oben/V2 1.016: R307.1 177.55,144.78 176.28,143.51 176.28,142.24 R309.2 | C303.2 168.66,142.24 R314.2
  Unten/V1 1.016: 171.2,139.7 171.2,135.89 167.39,132.08 G308.2 | 171.2,139.7 168.66,142.24 C303.2 | 171.2,139.7 R309.2
N$110
  Oben/V2 1.016: V306.2 175.01,149.86 176.28,148.59 176.28,146.05 175.01,144.78 R307.2 172.47,144.78 171.2,143.51 171.2,140.97 169.93,139.7 166.12,139.7 | 166.12,139.7 C307.1 | R315.1 166.12,139.7
N$111
  Oben/V2 1.016: 168.66,170.18 V303.1 | G303.2 168.66,170.18 | 168.66,170.18 G302.2
  Unten/V1 1.016: 175.01,165.1 R303.1 169.93,165.1 168.66,166.37 G303.2 | 175.01,165.1 177.55,167.64 R302.1 | 175.01,165.1 176.28,163.83 176.28,162.56 178.82,160.02 V304.1
N$112
  Oben/V2 1.016: IC301.3 168.66,147.32 V306.1
N$113
  Oben/V2 1.524: V301.1 166.12,193.04 166.12,185.42 163.58,182.88 G306.2 172.47,172.72 173.74,171.45 V303.2
N$114
  Oben/V2 1.524: 176.28,172.72 183.9,180.34 R301.1 | G302.1 171.2,177.8 176.28,172.72 | 176.28,172.72 V303.3
  Unten/V1 3.302: 181.36,195.58 178.82,198.12 175.01,198.12 171.2,194.31 V301.2 169.93,194.31 169.93,196.85 173.74,200.66 180.09,200.66 183.9,196.85 G301.1 | 181.36,195.58 181.36,187.96 R301.1 G301.1 | G301.1 181.36,195.58
N$115
  Oben/V2 1.016: V304.2 R304.1
  Unten/V1 1.016: R304.1 R303.2
N$116  (via drill 0.9 pad 1.5)
  Oben/V2 1.016: 110.24,172.72 112.78,172.72 115.32,175.26 v143.26,175.26 | G324.2 102.62,152.4 108.97,152.4 110.24,153.67 110.24,166.37 108.97,167.64 | V315.1 105.16,175.26 107.7,172.72 110.24,172.72 | 110.24,172.72 G321.2 110.24,168.91 108.97,167.64 | 108.97,167.64 R333.1
  Unten/V1 1.016: G324.2 T2.A1
N$117
  Unten/V1 1.016: R305.2 C302.2 | R305.2 R311.1 | IC301.1 R305.2
N$118
  Oben/V2 2.794: 140.72,194.31 139.45,195.58 139.45,184.15 C308.2 | 140.72,196.85 137.93,199.64 | 140.72,194.31 140.72,196.85 | C308.2 140.72,194.31 | 140.72,196.85 143.26,194.31 143.26,185.42 C308.2
  Oben/V2 3.302: 139.45,195.58 137.67,197.36 133.86,197.36 133.35,196.85 124.21,196.85 T302.3 124.21,199.39 128.02,199.39 | 128.02,199.39 T302.4 | 128.02,199.39 136.91,199.39
  Unten/V1 1.524: C308.2 139.45,181.61 R317.2 G310.2 | 140.72,193.04 137.93,195.83 137.93,196.85 | 125.48,196.85 G315.1
  Unten/V1 2.54: 140.72,193.04 V302.3
  Unten/V1 2.794: 140.72,196.85 137.93,196.85 | 140.72,196.85 138.18,199.39 137.93,199.39 | 140.72,193.04 140.72,196.85 | 140.72,184.15 C308.2 143.26,185.42 143.26,194.31 140.72,196.85
  Unten/V1 3.302: 137.93,196.85 137.42,197.36 133.86,197.36 133.35,196.85 128.02,196.85 | 128.02,196.85 T302.4 | 137.93,199.39 124.21,199.39 T302.3 124.21,196.85 125.48,196.85 128.02,196.85 | 140.72,184.15 140.72,193.04
N$120
  Unten/V1 1.016: R319.2 V310.1
N$121
  Oben/V2 1.016: R320.1 V310.2
  Unten/V1 1.016: G312.1 136.91,139.7 135.64,140.97 R320.1 V313.3
N$122
  Oben/V2 1.016: V311.1 V310.3
N$123
  Oben/V2 1.016: V311.2 125.48,147.32 125.48,146.05 126.75,144.78 R326.1
  Unten/V1 1.016: R326.1 R320.2
N$124
  Oben/V2 1.016: R316.2 148.34,137.16 G312.2 140.72,139.7 V313.2 | V313.2 140.72,144.78 140.72,148.59 138.18,151.13 C312.1 | C310.2 135.64,140.97 136.91,142.24 V313.2
  Unten/V1 1.016: C312.1 R318.1
N$125
  Oben/V2 1.016: R324.2 122.94,162.56 V309.2
  Unten/V1 1.016: R324.2 R323.1
N$126
  Unten/V1 1.016: G316.1 G317.1 130.56,166.37 129.29,165.1 R323.2 124.21,165.1 | V308.1 R322.2 121.67,167.64 124.21,165.1 | 124.21,165.1 122.94,163.83 V309.1
N$127
  Oben/V2 3.302: 135.64,191.52 V302.2 | 135.64,191.52 125.23,181.1 119.64,181.1 116.59,184.15 116.59,185.42 R321.2 114.05,185.42 114.05,182.88 118.37,178.56 126.5,178.56 135.64,187.71 135.64,191.52
  Unten/V1 1.016: 125.48,172.72 G316.2
  Unten/V1 1.524: V308.3 125.48,172.72 115.32,182.88 R321.2 G315.2
N$128
  Oben/V2 1.524: V308.2 122.94,171.45 124.21,172.72 G311.1
  Unten/V1 1.524: V302.1 130.56,193.04 130.56,181.61 135.64,176.53 G311.1
N$129
  Unten/V1 1.016: R325.1 V312.1
N$130
  Oben/V2 1.016: R327.1 128.02,137.16 G319.2
N$131
  Unten/V1 1.016: V312.2 125.48,140.97 124.21,139.7 | R328.2 124.21,139.7 | G319.1 125.48,138.43 124.21,139.7
N$132
  Oben/V2 1.016: R326.2 124.21,144.78 125.48,143.51 125.48,142.24 R328.1
  Unten/V1 1.016: C313.1 133.1,139.7 R328.1 128.02,138.43 134.37,132.08 G313.1
N$133
  Unten/V1 1.016: C301.1 R302.2
N$134
  Unten/V1 1.016: R322.1 C311.2
N$135
  Oben/V2 1.016: C306.1 166.12,147.32 166.12,144.78 | 166.12,144.78 R313.1 | 166.12,144.78 168.66,144.78 C303.1
  Unten/V1 1.016: R308.1 172.47,142.24 169.93,144.78 | C303.1 168.66,144.78 169.93,144.78 | V307.E 159.77,151.13 C306.1 | R306.1 172.47,147.32 169.93,144.78
  Unten/V1 1.524: C306.1 159.77,158.75 G307.2
N$136
  Oben/V2 1.524: C309.2 143.26,154.94 G310.1
  Unten/V1 1.016: 133.1,144.78 130.56,147.32 R325.2 | 133.1,144.78 C309.2 | 133.1,142.24 133.1,144.78 | 133.1,142.24 C313.2 | R327.2 133.1,142.24
N$137
  Oben/V2 1.016: V306.3 171.2,154.94 G304.2
N$138
  Unten/V1 1.016: R314.1 V307.C
N$139
  Oben/V2 1.016: R313.2 155.96,142.24 V307.B
  Unten/V1 1.016: R313.2 R312.1
N$141
  Unten/V1 1.016: V311.3 G318.1
N$142  (via drill 0.9 pad 1.5)
  Oben/V2 1.016: 81.03,167.64 79.76,166.37 79.76,156.21 81.03,154.94 G124.2 | 81.03,167.64 79.76,168.91 G121.2 79.76,175.26 | 81.03,167.64 R133.2 | 79.76,175.26 V115.1 | 79.76,175.26 55.63,175.26 53.09,177.8 v49.28,177.8
  Unten/V1 1.016: G124.2 T1.A1
N$143
  Oben/V2 1.016: R108.2 16.26,137.16 G105.1
N$144
  Unten/V1 1.016: V105.2 13.72,140.97 12.45,139.7 | R109.1 12.45,139.7 | 12.45,139.7 13.72,138.43 G105.2
N$145
  Unten/V1 1.016: R106.2 V105.1
N$146
  Oben/V2 1.016: R107.1 12.45,144.78 13.72,143.51 13.72,142.24 R109.2 | C103.2 21.34,142.24 R114.2
  Unten/V1 1.016: 18.8,139.7 18.8,135.89 22.61,132.08 G108.2 | 18.8,139.7 21.34,142.24 C103.2 | 18.8,139.7 R109.2
N$147
  Oben/V2 1.016: V106.2 13.72,147.32 13.72,146.05 14.99,144.78 R107.2 17.53,144.78 18.8,143.51 18.8,140.97 20.07,139.7 23.88,139.7 | 23.88,139.7 C107.1 | 23.88,139.7 R115.1
N$148
  Unten/V1 1.016: R102.1 14.99,167.64 17.53,165.1 R103.1 22.61,165.1 23.88,166.37 G102.2 | R102.1 11.18,165.1 G103.2 V104.1 | R102.1 V103.1
N$149
  Unten/V1 1.016: V106.1 IC101.3
N$150
  Oben/V2 1.524: V103.2 16.26,172.72 9.91,179.07 9.91,189.23 13.72,193.04 V101.1
  Unten/V1 1.524: V101.1 13.72,193.04 13.72,191.26 11.18,188.72 11.18,184.15 13.72,181.61 23.88,181.61 26.42,179.07 G106.2
N$151
  Oben/V2 1.524: V103.3 G102.1 22.61,176.53 22.61,187.96 18.8,191.77 V101.2
  Oben/V2 3.302: R101.1 G101.1 8.64,198.12 16.26,198.12 18.8,195.58 V101.2
  Unten/V1 3.302: G101.1 R101.1 6.1,188.72 8.64,191.26 8.64,195.58 | 8.64,195.58 11.18,198.12 16.26,198.12 18.8,195.58 V101.2 18.8,194.31 20.07,195.58 20.07,198.12 17.53,200.66 9.91,200.66 6.1,196.85 G101.1 | G101.1 8.64,195.58
N$152
  Unten/V1 1.016: V104.2 R104.1 R103.2
N$153  (via drill 3.2 pad 5.99)
  other vias: 135.64,219.71
N$154
  Unten/V1 1.016: R105.2 R111.1 | IC101.1 21.34,154.94 R105.2 | R105.2 C102.2
N$155
  Unten/V1 1.016: IC305.4 112.78,27.94 G336.1 G337.1
N$156  (via drill 3.2 pad 5.99)
  other vias: 171.2,219.71
N$157
  Unten/V1 1.016: R118.2 V110.1
N$158
  Unten/V1 1.016: V110.2 56.9,147.32 54.36,144.78 54.36,143.51 53.09,142.24 V113.3 G115.1 R127.1
N$159
  Unten/V1 1.016: V111.1 59.44,151.13 58.17,152.4 V110.3
N$160
  Oben/V2 1.016: R125.1 63.25,144.78 64.52,146.05 64.52,147.32 V111.2
  Unten/V1 1.016: R125.1 60.71,144.78 59.44,143.51 R127.2
N$161
  Oben/V2 1.016: R116.2 41.66,137.16 G115.2 49.28,139.7 | V113.2 49.28,142.24 49.28,139.7 | C110.2 51.82,137.16 49.28,139.7
  Unten/V1 1.016: C112.1 R123.1 56.9,154.94 51.82,149.86 V113.2
N$162
  Unten/V1 1.016: R121.1 R122.2 V109.2
N$163
  Unten/V1 1.016: V109.1 64.52,167.64 | 64.52,167.64 R120.2 R121.2 | G113.1 V108.1 64.52,167.64 | G113.1 G112.1 G113.1
N$164
  Oben/V2 1.524: R119.2 G119.2
  Oben/V2 3.302: 54.36,191.26 V102.2 | 54.36,191.26 64.52,181.1 70.36,181.1 73.41,184.15 73.41,185.42 R119.2 75.95,185.42 75.95,182.88 71.63,178.56 63.25,178.56 54.36,187.45 54.36,191.26
  Unten/V1 1.524: 69.6,172.72 64.52,177.8 G112.2 | 69.6,172.72 V108.3 | R119.2 74.68,177.8 69.6,172.72
N$165
  Oben/V2 1.524: V102.1 49.28,193.04 46.74,190.5 46.74,176.53 48.01,175.26 51.82,175.26 G111.1
  Unten/V1 1.524: G111.1 65.79,172.72 67.06,171.45 V108.2
N$166
  Oben/V2 1.016: R124.1 V112.1
N$167
  Oben/V2 1.016: R126.1 61.98,137.16 G116.2
N$168
  Unten/V1 1.016: V112.2 64.52,147.32 64.52,140.97 65.79,139.7 | 65.79,139.7 R128.2 | G116.1 64.52,138.43 65.79,139.7
N$169
  Oben/V2 1.016: C113.1 56.9,142.24 59.44,142.24 R128.1 64.52,142.24 64.52,143.51 65.79,144.78 R125.2
  Unten/V1 1.016: G117.1 55.63,132.08 61.98,138.43 R128.1
N$170
  Unten/V1 1.016: R102.2 C101.1
N$171
  Unten/V1 1.016: C111.2 R120.1
N$172
  Oben/V2 1.016: C106.1 27.69,153.67 26.42,152.4 26.42,149.86 23.88,147.32 23.88,144.78 | 23.88,144.78 R113.1 | C103.1 21.34,144.78 23.88,144.78
  Unten/V1 1.016: R108.1 17.53,142.24 20.07,144.78 | 20.07,144.78 21.34,144.78 C103.1 | C106.1 30.23,152.4 34.04,148.59 V107.E | R106.1 17.53,147.32 20.07,144.78
  Unten/V1 1.524: C106.1 30.23,158.75 G107.2
N$173
  Oben/V2 1.016: 59.44,144.78 59.44,146.05 60.71,147.32 R124.2 | 59.44,144.78 R126.2 | 56.9,144.78 59.44,144.78 | C113.2 56.9,144.78 | C109.2 51.82,149.86 51.82,147.32 54.36,144.78 56.9,144.78
  Unten/V1 1.524: C109.2 48.01,161.29 G110.1
N$174
  Oben/V2 1.016: V106.3 18.8,154.94 G104.2
N$175
  Unten/V1 1.016: R114.1 V107.C
N$176
  Oben/V2 1.016: R113.2 V107.B
  Unten/V1 1.016: R113.2 R112.1
N$177  (via drill 0.9 pad 1.5)
  Unten/V1 1.016: R112.2 26.42,158.75 28.96,161.29 28.96,163.07 26.42,165.61 26.42,168.91 20.07,175.26 11.18,175.26 2.29,184.15 2.29,210.82 16.26,224.79 75.95,224.79 U$200.1 78.49,224.79 98.81,224.79 | R312.2 163.58,158.75 161.04,161.29 161.04,163.83 164.85,167.64 166.12,167.64 168.66,170.18 168.66,171.45 175.01,177.8 181.36,177.8 187.71,184.15 187.71,210.82 173.74,224.79 98.81,224.79 | 98.81,224.79 v98.81,219.71
N$178
  Oben/V2 1.016: G114.1 58.17,154.94 60.71,152.4 V111.3
N$179
  Oben/V2 1.016: P301.2 148.34,60.96 R364.1
  Unten/V1 1.016: P301.2 P301.S
N$180
  Unten/V1 1.016: T2.A2 G324.1 102.87,154.94 101.35,156.46 101.35,158.5 102.62,159.77 102.62,162.56 100.08,165.1 V317.1 R332.1 R331.1
N$181
  Unten/V1 1.524: G325.2 G328.2 176.28,57.15 169.93,50.8 V319.2
N$182
  Oben/V2 1.016: R407.2 96.27,29.21 96.27,72.39 97.54,73.66 97.54,155.19 98.81,156.46 98.81,157.48 | 98.81,157.48 J305.1 | C315.1 98.81,157.48
  Unten/V1 1.016: C315.1 98.81,157.48 98.81,158.75 G323.1
N$183
  Oben/V2 1.016: V315.3 111.51,175.26 112.78,176.53 112.78,179.07 111.51,180.34 R329.2
N$184
  Oben/V2 1.016: V114.2 89.92,182.88 G120.2
  Unten/V1 1.016: G123.2 83.57,160.02 84.84,161.29 84.84,162.56 R134.1 R133.1 89.92,170.18 89.92,177.8 V114.2
N$185
  Unten/V1 1.016: R372.2 131.83,7.62 130.56,8.89 R382.2 R383.1
N$186
  Unten/V1 1.016: J306.2 100.08,121.92 | R408.2 105.16,120.65 103.89,121.92 100.08,121.92 | 100.08,121.92 T2.14
N$187
  Oben/V2 1.016: V119.1 22.61,48.26 23.88,49.53 23.88,54.61 25.15,55.88 31.5,55.88 32.01,56.39 38.1,56.39 39.12,55.37 V123.1
  Unten/V1 1.016: R166.1 44.2,52.07 42.93,50.8 40.39,50.8 39.12,52.07 V123.1 39.12,57.15 R163.1 | V120.2 20.07,35.56 16.26,39.37 16.26,44.45 20.07,48.26 V119.1
N$188
  Unten/V1 1.016: J106.2 R208.2 82.3,121.92 T1.14
N$189
  Oben/V2 1.016: V115.3 84.84,179.07 83.57,180.34 R129.1
N$190
  Unten/V1 1.016: T1.A2 G124.1 88.65,156.21 88.65,158.75 87.38,160.02 87.38,162.56 V117.1 89.92,167.64 R132.1 R131.1
N$200
  Unten/V1 1.016: R330.1 R331.2 V316.3
N$201
  Unten/V1 1.524: G311.2 138.18,165.1 R317.1
N$202
  Oben/V2 1.524: G111.2 51.82,165.1 R117.1
N$203
  Oben/V2 1.524: G106.1 28.96,165.1 R110.2
N$204
  Oben/V2 1.016: P101.1 37.85,66.04 36.58,64.77 36.58,60.96 41.66,55.88 | V123.3 34.04,50.8 35.31,49.53 40.39,49.53 41.66,50.8 R160.1 41.66,55.88 | 41.66,55.88 R165.1
  Unten/V1 1.016: P101.1 R162.1
N$205
  Unten/V1 1.016: R163.2 R164.2 50.55,58.42 51.82,57.15 R173.1 | R173.1 V126.3 | R166.2 R173.1
N$206
  Oben/V2 1.016: V317.2 100.08,170.18 R332.2 105.16,167.64 V316.1
N$208
  Unten/V1 1.016: V314.1 R329.1 102.62,177.8 107.7,172.72 V316.2 105.16,165.1 G322.2
N$209
  Unten/V1 1.016: G122.2 84.84,165.1 84.84,170.18 V116.2 87.38,177.8 R129.2 V114.1
N$210
  Oben/V2 1.016: V314.2 102.62,177.8 105.16,180.34 G320.2
  Unten/V1 1.016: V314.2 100.08,170.18 R333.2 R334.1 G323.2
N$211  (via drill 0.9 pad 1.5)
  Unten/V1 1.016: G121.1 V115.2 89.92,185.42 v98.81,185.42 100.08,185.42 V315.2 G321.1
N$214
  Unten/V1 1.016: G139.2 G138.2 IC105.8
N$215
  Unten/V1 1.016: 105.16,10.16 G339.1 | 105.16,10.16 J4.1 | G139.1 105.16,10.16
N$216
  Oben/V2 1.016: IC305.8 122.94,19.05 121.67,20.32 112.78,20.32 G338.2
  Unten/V1 1.016: G339.2 G338.2
N$218
  Oben/V2 1.016: P101.2 41.66,60.96 R164.1
  Unten/V1 1.016: P101.S P101.2
N$219
  Unten/V1 1.016: R198.2 V132.3
N$220
  Unten/V1 1.524: V119.2 16.26,50.8 8.64,58.42 G128.2 G125.2
N$221
  Unten/V1 1.524: R146.2 6.1,71.12 11.18,66.04 12.45,66.04 G125.1
N$222
  Oben/V2 1.016: G103.1 11.18,162.56 13.72,160.02 C102.1 17.53,160.02 18.8,158.75 18.8,157.48 G104.1
  Unten/V1 1.016: V105.3 G104.1
N$223
  Unten/V1 1.016: V112.3 64.52,152.4 G114.2 60.71,154.94 59.44,156.21 59.44,158.75 60.71,160.02 | 60.71,160.02 C112.2 | G113.2 59.44,161.29 60.71,160.02
N$224
  Unten/V1 1.016: R348.1 V319.3
N$225
  Unten/V1 1.524: G331.2 107.7,66.04 102.62,71.12 R405.1
N$226
  Unten/V1 1.524: V332.2 112.78,50.8 105.16,58.42 G333.1 G331.1
N$227
  Unten/V1 1.016: V327.3 125.48,58.42 R397.1
N$228
  Unten/V1 1.016: V327.1 V328.3 122.94,44.45 124.21,43.18 G334.1 R399.2
N$229
  Oben/V2 1.016: R398.2 116.59,45.72 115.32,46.99 115.32,52.07 116.59,53.34 V332.3
N$230
  Oben/V2 1.016: G303.1 171.2,157.48 | 171.2,157.48 173.74,160.02 C302.1 | 171.2,157.48 G304.1
  Unten/V1 1.016: G304.1 V305.3
N$231
  Unten/V1 1.016: G318.2 124.21,154.94 125.48,153.67 | 125.48,153.67 V312.3 | 125.48,153.67 129.29,157.48 130.56,157.48 | 130.56,157.48 C312.2 | 130.56,157.48 G317.2
N$530
  Unten/V1 1.016: R306.2 V305.1
OFFSET1
  Unten/V1 1.016: R203.1 IC105.7 74.68,19.05 75.95,20.32 78.49,20.32 84.84,26.67 MP15.1 R207.1
OFFSET2
  Unten/V1 1.016: R402.1 IC305.7 120.4,18.8 118.88,20.32 114.05,20.32 111.51,22.86 108.97,22.86 105.16,26.67 MP16.1 R407.1

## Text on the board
Oben/V2: Weiten 09 | Endverstärker/ | Netzgerät
Unten/V1: Weiten 09 | Endverstärker/ | Netzgerät
A1-PL/V2: Ein/Aus
Namen/obe: -UB | GND | +UB | Masse | +UB1 | MASSE | -UB1 | -UB2 | +UB2 | -LED | +LED | -LED | +LED | -MHT | -TT | -MHT | MHT- und TT(MHT)-Endstufe | +MHT/+TT | +MHT | Ruhestrom | Ruhestrom | B | E | E | B | B | E | E | B | -15V | +15V | NF-Eingang | NF-Eingang
Bemaáung: 190 | 123,0 | 50,8 | 16,3 | 50,8 | 6 | 226,1 | 186,7 | 185,2 | 153,4 | 56,9 | 36,6 | 4,8 | 6 | 50,8 | 43,2 | 35,6 | 3,2 | 22 | 5 | 5 | 5 | 82,3 | 95 | 107,7 | 133,1 | 185
Hilfstext: Kupferauflage 70 µm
